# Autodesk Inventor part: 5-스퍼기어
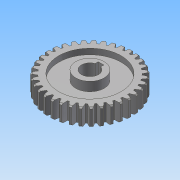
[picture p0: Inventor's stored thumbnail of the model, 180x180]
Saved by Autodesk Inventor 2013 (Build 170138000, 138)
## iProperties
Created: 2013-08
Part Number: 5-스퍼기어
Material: 강
Document SubType Name: Modeling
Designer: 한국산업디자인학원
Categories: <?xml version="1.0" encoding="UTF-16"?> <MemberInstance><Categories><FamilyTemplate><FamilyTemplateParameter ValueType="xs:double" Id="1" ObjectReferenceKey="da
Density: 1 g/cm^3
CustomPartVersion: 1
Author: 한국산업디자인학원
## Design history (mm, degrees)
sketch "Sketch1"
  geometry: C1 r 37 at (0, 0)
  constraints: 1 centre point
  dimensions: "d0" = 74 diameter of C1 (= da_da)
extrude "Extrusion1" new body sketch "Sketch1" distance "d1" = 15 (= da_b); taper "d2" = 0 deg
chamfer "모따기1" distance "d49" = 1; stored, may be unused: second distance "d50" = 2, angle "d51" = 45 deg
workplane "Work Plane2"
feature "피치 지름" dims "d4" = 10, "d5" = 0
workplane "Work Plane8"
workplane "Work Plane9"
feature "스퍼 기어" dims "da_b" = 15, "da_d" = 70, "da_aw" = 70, "da_da" = 74, "da_df" = 65, "da_dw" = 70, angle "da_beta" = 0 deg, "da_lefttooth" = 0, "da_righttooth" = 0
sketch "스케치3"
  geometry: C1 r 12.5 at (0, 0); A1 r 32.5 centre (0, 0) between (9.347, 31.127) and (7.941, 31.515) reference
  constraints: 1 centre point, 1 coincident
  dimensions: "d52" = 25 diameter of C1
extrude "돌출2" join sketch "스케치3" distance "d54" = 13; taper "d55" = 0 deg
sketch "스케치4"
  geometry: C1 r 12.5 at (0, 0); A1 r 36 centre (0, 0) between (-5.215, 35.62) and (-7.633, 35.181) reference
  constraints: 1 centre point, 1 coincident
  dimensions: "d56" = 25 diameter of C1
extrude "돌출3" join sketch "스케치4" distance "d58" = 3; taper "d59" = 0 deg
sketch "스케치5"
  geometry: C1 r 12.5 at (0, 0) reference; C2 r 27.5 at (0, 0); C3 r 12.5 at (0, 0) reference; C4 r 12.5 at (0, 0); A1 r 32.5 centre (0, 0) between (9.347, 31.127) and (7.941, 31.515) reference
  constraints: 2 centre point, 2 coincident
  dimensions: "d60" = 55 diameter of C2; "d62" = 25 diameter of C4
extrude "돌출4" cut sketch "스케치5" distance "d63" = 5; taper "d64" = 0 deg
sketch "스케치6"
  geometry: C1 r 12.5 at (0, 0) reference; C2 r 12.5 at (0, 0); C3 r 27.5 at (0, 0); A1 r 36 centre (0, 0) between (-5.215, 35.62) and (-7.633, 35.181) reference
  constraints: 2 centre point, 2 coincident, 1 concentric
  dimensions: "d65" = 55 diameter of C3
extrude "돌출5" cut sketch "스케치6" distance "d67" = 5; taper "d68" = 0 deg
sketch "스케치7"
  geometry: L1 (-2.5, 7.071)-(-2.5, 9.8); L2 (-2.5, 9.8)-(2.5, 9.8); L3 (2.5, 9.8)-(2.5, 7.071); C1 r 12.5 at (0, 0) reference; A1 r 7.5 centre (0, 0) between (-2.5, 7.071) and (2.5, 7.071)
  constraints: 6 end point, 2 parallel, 2 point on circle, 1 centre point, 1 coincident, 1 perpendicular, 1 vertical
  dimensions: "d69" = 15 diameter of A1; "d71" = 5 distance of L1.end L2.end; "d72" = 17.3 dimension on A1 L2
extrude "돌출6" cut sketch "스케치7" stored distance "d73" = 5; taper "d74" = 0 deg
fillet "모깎기1" dims "d75" = 3
body "Solid1"
sketch "Sketch2"
  geometry: C1 r 37 at (0, 0) reference; C2 r 35 at (0, 0)
  constraints: 1 centre point, 1 coincident
  dimensions: "d3" = 70 diameter of C2 (= da_dw)
body "Srf1"
other parameters: "d17" = 0, "d34" = 0.8976 (computed from da_z), "d39" = 0, "d41" = 0, "d47" = 0, "d48" = 0
